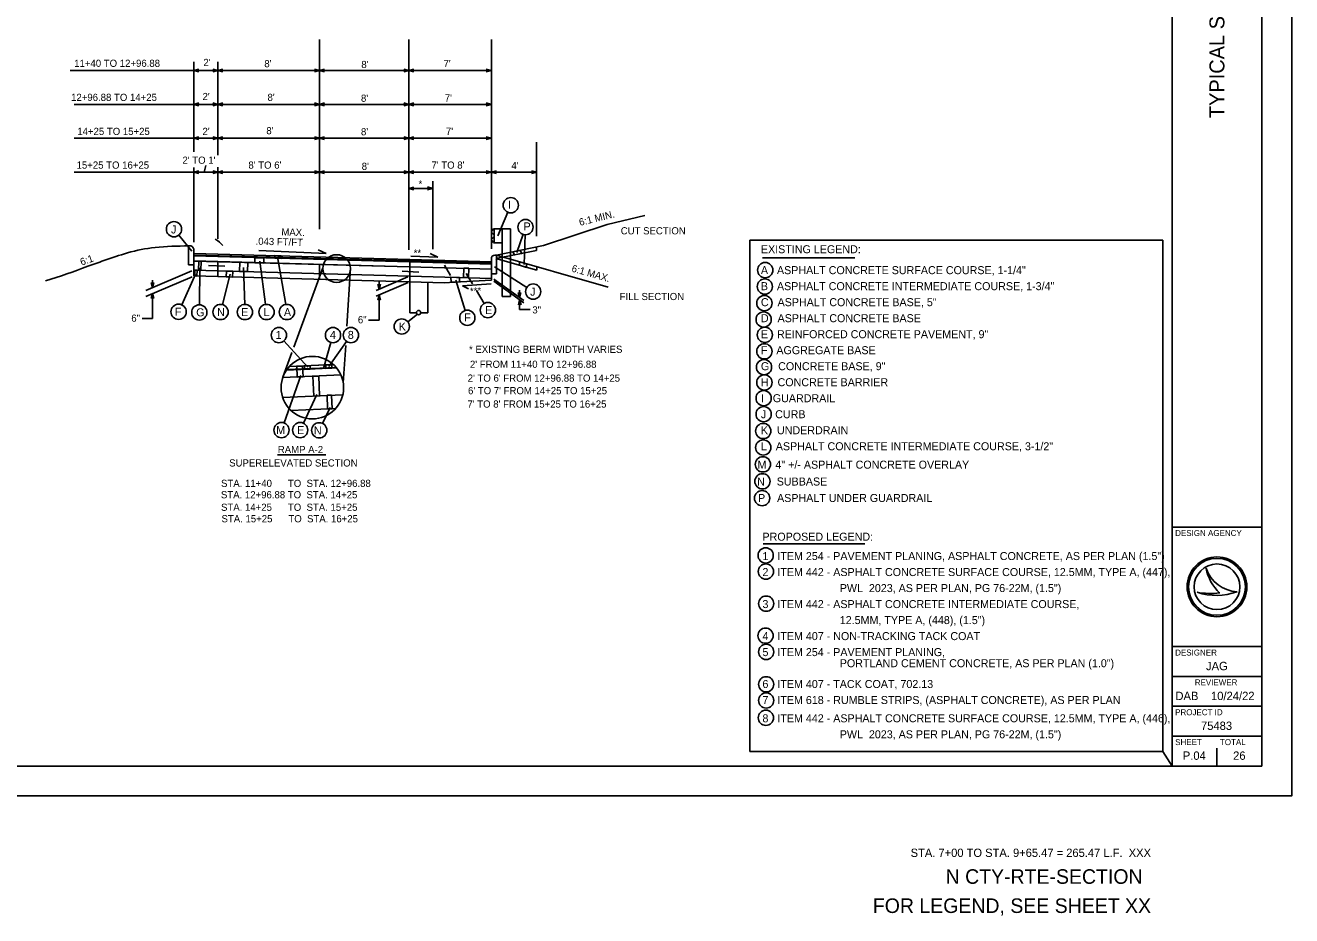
# Model space of a CAD drawing. Extents: x -196 to 300, y -73 to 205.
# Drawn here: x 64 to 170, y -10 to 64.5 of the extents above; entities that cross this region are included whole.
import ezdxf

# ---------------------------------------------------------------- set-up
doc = ezdxf.new("R2010")
doc.units = 0
for name, color, linetype in [('Level 4', 7, 'Continuous'), ('Level 59', 7, 'Continuous'), ('Level 6', 7, 'Continuous'), ('Level 60', 7, 'Continuous'), ('Level 7', 7, 'Continuous'), ('SH_Border', 7, 'Continuous'), ('SH_Cut_Line', 7, 'Continuous'), ('SH_Data', 7, 'Continuous')]:
    doc.layers.add(name, color=color, linetype=linetype)

msp = doc.modelspace()

# ---------------------------------------------------------------- linework, layer by layer
at = {"layer": 'Level 4'}
for p, q in [((88.63, 47.44), (88.63, 63.3)), ((96.11, 45.71), (96.11, 63.3)), ((103.02, 45.78), (103.02, 63.3)), ((67.78, 60.72), (78.13, 60.72)), ((78.13, 53.92), (78.13, 61.44)), ((78.13, 60.72), (80.13, 60.72)), ((80.13, 53.63), (80.13, 61.44)), ((80.13, 60.72), (88.63, 60.72)), ((88.48, 60.74), (88.9, 60.74)), ((88.63, 60.72), (96.11, 60.72)), ((96.11, 60.72), (103.02, 60.72)), ((68.11, 57.88), (78.13, 57.88)), ((78.13, 57.88), (80.13, 57.88)), ((80.13, 57.88), (88.63, 57.88)), ((88.48, 57.9), (88.9, 57.9)), ((88.63, 57.88), (96.11, 57.88)), ((96.11, 57.88), (103.02, 57.88)), ((68.11, 55.04), (78.13, 55.04)), ((78.13, 55.04), (80.13, 55.04)), ((80.13, 55.04), (88.63, 55.04)), ((80.13, 54.28), (80.13, 54.67)), ((88.48, 55.06), (88.9, 55.06)), ((88.63, 55.04), (96.11, 55.04)), ((96.11, 55.04), (103.02, 55.04)), ((106.81, 46.86), (106.81, 54.72)), ((68.11, 52.2), (78.13, 52.2)), ((78.13, 46.34), (78.13, 52.59)), ((78.13, 52.2), (80.13, 52.2)), ((79.12, 52.76), (79, 52.21)), ((80.13, 46.63), (80.13, 52.62)), ((80.13, 52.2), (88.63, 52.2)), ((88.48, 52.22), (88.9, 52.22)), ((88.63, 52.2), (96.11, 52.2)), ((96.11, 52.2), (106.81, 52.2)), ((98.11, 45.75), (98.11, 51.45)), ((96.11, 50.85), (98.11, 50.85)), ((83.56, 45.65), (89.19, 45.4)), ((89.19, 45.4), (88.52, 45.72)), ((96.29, 45.17), (98.55, 45.09)), ((98.55, 45.09), (97.89, 45.41)), ((77.95, 43.94), (74.11, 42.31)), ((77.98, 43.46), (74.11, 41.81)), ((74.67, 42.54), (74.67, 43.17)), ((96.03, 43.44), (93.37, 42.31)), ((96.06, 42.96), (93.39, 41.82)), ((93.63, 42.42), (93.63, 43.05)), ((100.6, 42.69), (103, 42.86)), ((100.6, 42.69), (101.12, 42.43)), ((103.22, 43.25), (105.74, 41.46)), ((103.22, 43.07), (105.75, 41.28)), ((74.67, 39.95), (74.67, 42.05)), ((93.63, 39.82), (93.63, 41.92)), ((105.38, 41.71), (105.38, 42.34)), ((105.39, 40.71), (105.39, 41.53)), ((106.27, 40.71), (105.39, 40.71)), ((73.79, 39.95), (74.67, 39.95)), ((92.75, 39.82), (93.63, 39.82)), ((85.12, 28.55), (89.18, 28.55))]:
    msp.add_line(p, q, dxfattribs=at)
for points in [[(78.55, 60.61), (78.13, 60.72), (78.55, 60.83)], [(79.71, 60.84), (80.13, 60.72), (79.71, 60.61)], [(80.55, 60.61), (80.13, 60.72), (80.55, 60.83)], [(88.21, 60.84), (88.63, 60.72), (88.21, 60.61)], [(89.05, 60.61), (88.63, 60.72), (89.05, 60.83)], [(95.69, 60.84), (96.11, 60.72), (95.69, 60.61)], [(96.53, 60.61), (96.11, 60.72), (96.53, 60.83)], [(102.6, 60.84), (103.02, 60.72), (102.6, 60.61)], [(78.55, 57.77), (78.13, 57.88), (78.55, 58)], [(79.71, 58), (80.13, 57.88), (79.71, 57.77)], [(80.55, 57.77), (80.13, 57.88), (80.55, 58)], [(88.21, 58), (88.63, 57.88), (88.21, 57.77)], [(89.05, 57.77), (88.63, 57.88), (89.05, 58)], [(95.69, 58), (96.11, 57.88), (95.69, 57.77)], [(96.53, 57.77), (96.11, 57.88), (96.53, 58)], [(102.6, 58), (103.02, 57.88), (102.6, 57.77)], [(78.55, 54.93), (78.13, 55.04), (78.55, 55.16)], [(79.71, 55.16), (80.13, 55.04), (79.71, 54.93)], [(80.55, 54.93), (80.13, 55.04), (80.55, 55.16)], [(88.21, 55.16), (88.63, 55.04), (88.21, 54.93)], [(89.05, 54.93), (88.63, 55.04), (89.05, 55.16)], [(95.69, 55.16), (96.11, 55.04), (95.69, 54.93)], [(96.53, 54.93), (96.11, 55.04), (96.53, 55.16)], [(102.6, 55.16), (103.02, 55.04), (102.6, 54.93)], [(78.55, 52.09), (78.13, 52.2), (78.55, 52.32)], [(79.71, 52.32), (80.13, 52.2), (79.71, 52.09)], [(80.55, 52.09), (80.13, 52.2), (80.55, 52.32)], [(88.21, 52.32), (88.63, 52.2), (88.21, 52.09)], [(89.05, 52.09), (88.63, 52.2), (89.05, 52.32)], [(95.69, 52.32), (96.11, 52.2), (95.69, 52.09)], [(96.53, 52.09), (96.11, 52.2), (96.53, 52.32)], [(102.6, 52.32), (103.02, 52.2), (102.6, 52.09)], [(103.44, 52.09), (103.02, 52.2), (103.44, 52.32)], [(106.39, 52.32), (106.81, 52.2), (106.39, 52.09)], [(96.53, 50.73), (96.11, 50.85), (96.53, 50.96)], [(97.69, 50.97), (98.11, 50.85), (97.69, 50.74)], [(74.78, 42.96), (74.67, 42.54), (74.56, 42.96)], [(93.74, 42.84), (93.63, 42.42), (93.51, 42.84)], [(74.55, 41.63), (74.67, 42.05), (74.78, 41.63)], [(93.51, 41.5), (93.63, 41.92), (93.74, 41.5)], [(105.27, 42.13), (105.38, 41.71), (105.49, 42.13)], [(105.51, 41.11), (105.39, 41.53), (105.28, 41.11)]]:
    msp.add_lwpolyline(points, dxfattribs=at)
for points in [[(104.83, 45.54), (105.44, 45.66), (105.57, 45.4), (104.96, 45.28)], [(105.37, 44.7), (105.97, 44.53), (105.97, 44.24), (105.37, 44.41)]]:
    msp.add_lwpolyline(points, close=True, dxfattribs=at)
at = {"layer": 'Level 59'}
for p, q in [((103.57, 46.87), (104.4, 48.85)), ((77.95, 45.6), (76.86, 46.93)), ((105.16, 45.48), (105.68, 47.01)), ((105.77, 44.48), (105.86, 46.98)), ((84.12, 41.14), (83.65, 44.77)), ((85.81, 41.13), (85.13, 45.11)), ((125.72, 45.04), (133.45, 45.04)), ((77.11, 41.1), (78.27, 43.66)), ((78.59, 41.11), (78.63, 44.2)), ((80.52, 41.12), (81.15, 43.66)), ((82.38, 41.14), (82.29, 44.23)), ((100.92, 43.73), (101.44, 42.86)), ((103.28, 44.28), (105.98, 42.55)), ((100.04, 43.17), (100.83, 40.63)), ((101.77, 42.29), (102.41, 41.21)), ((96.83, 40.31), (96.02, 39.68)), ((85.66, 38.08), (87.66, 35.89)), ((89.59, 37.95), (88.98, 35.77)), ((90.91, 38.04), (89.43, 35.93)), ((85.67, 31.22), (87.07, 35.18)), ((87.29, 31.2), (88.42, 33.6)), ((88.9, 31.18), (89.53, 32.5)), ((125.78, 21.1), (134.29, 21.1)), ((159.22, 3.72), (160, 2.5))]:
    msp.add_line(p, q, dxfattribs=at)
for points in [[(78.5, 44), (78.53, 44.76), (78.74, 44.75), (78.72, 43.99)], [(78.2, 43.52), (78.21, 44.01), (78.39, 44), (78.38, 43.51)], [(89.18, 35.78), (89.67, 35.81), (89.66, 36.09), (89.17, 36.07)], [(86.78, 35.06), (87.27, 35.08), (87.22, 35.98), (86.73, 35.96)], [(87.38, 35.7), (87.86, 35.72), (87.86, 36.01), (87.37, 35.99)], [(88.16, 33.47), (88.65, 33.49), (88.57, 35.14), (88.09, 35.12)], [(89.32, 32.4), (89.7, 32.41), (89.65, 33.54), (89.27, 33.53)]]:
    msp.add_lwpolyline(points, close=True, dxfattribs=at)
for centre in [(104.65, 49.44), (76.46, 47.43), (105.88, 47.61), (125.94, 44.01), (106.52, 42.21), (125.91, 42.63), (125.87, 41.25), (76.85, 40.52), (78.58, 40.47), (80.36, 40.5), (82.4, 40.5), (84.21, 40.5), (85.91, 40.5), (101.01, 40.02), (102.73, 40.66), (125.81, 39.87), (95.52, 39.29), (125.91, 38.59), (85.24, 38.57), (89.77, 38.57), (91.27, 38.57), (125.87, 37.21), (125.84, 35.89), (125.87, 34.61), (125.81, 33.29), (125.81, 31.95), (85.46, 30.62), (87.02, 30.62), (88.62, 30.6), (125.78, 30.54), (125.78, 29.16), (125.75, 27.75), (125.71, 26.33), (125.68, 24.92), (125.98, 20.13), (126, 18.78), (126.02, 16.09), (125.97, 13.41), (126.02, 12.05), (126.02, 9.34), (126.02, 7.99), (126, 6.54)]:
    msp.add_circle(centre, 0.639, dxfattribs=at)
at = {"layer": 'Level 6'}
for p, q in [((107.38, 46.06), (112.7, 47.82)), ((112.7, 47.82), (115.87, 48.59)), ((103.04, 47.24), (103.19, 47.45)), ((103.24, 46.99), (103.05, 47.13)), ((103.05, 46.62), (103.24, 46.77)), ((103.19, 47.45), (103.27, 47.46)), ((103.94, 47.46), (103.27, 47.46)), ((103.27, 46.29), (103.27, 47.46)), ((103.94, 47.46), (103.94, 45.21)), ((103.94, 47.46), (104.61, 47.46)), ((104.61, 44.96), (104.61, 47.46)), ((77.68, 44.46), (77.68, 46.03)), ((77.68, 46.03), (77.86, 46.03)), ((78.13, 43.52), (78.13, 45.63)), ((103.19, 46.31), (103.04, 46.51)), ((103.19, 46.31), (103.27, 46.29)), ((103.94, 46.29), (103.27, 46.29)), ((103.41, 44.97), (106.81, 45.66)), ((103.44, 45.26), (107.38, 46.06)), ((106.81, 45.94), (106.81, 45.66)), ((78.13, 45.19), (96.19, 44.7)), ((78.13, 44.79), (96.15, 44.29)), ((78.13, 44.77), (96.19, 44.27)), ((80.13, 44.73), (80.13, 43.47)), ((96.19, 44.7), (103.03, 44.51)), ((96.19, 43.03), (96.19, 44.69)), ((103.03, 43.18), (103.03, 44.97)), ((103.31, 45.26), (103.44, 45.26)), ((103.41, 44.97), (106.82, 44.01)), ((103.44, 43.7), (103.44, 45.26)), ((103.44, 45.26), (112.8, 42.58)), ((103.94, 41.79), (103.94, 45.21)), ((104.61, 44.96), (104.61, 41.79)), ((77.68, 44.46), (78.13, 44.46)), ((78.13, 44.01), (80.13, 43.95)), ((80.13, 43.47), (78.13, 43.52)), ((79.35, 44.4), (80.72, 44.34)), ((80.13, 43.95), (96.19, 43.51)), ((80.13, 43.47), (96.19, 43.03)), ((88.63, 43.23), (88.63, 44.48)), ((95.57, 43.92), (96.95, 43.85)), ((96.15, 44.29), (103.03, 44.1)), ((96.19, 43.51), (103.03, 43.32)), ((103.03, 43.7), (103.44, 43.7)), ((106.82, 44.3), (106.82, 44.01)), ((96.19, 43.03), (99.08, 42.95)), ((96.19, 40.42), (96.19, 43.03)), ((97.7, 40.42), (97.7, 42.98)), ((99.08, 42.95), (100.43, 43.04)), ((100.43, 43.04), (103.03, 43.18)), ((104.61, 41.79), (103.94, 41.79)), ((96.19, 40.42), (96.75, 40.42)), ((97.11, 40.42), (97.7, 40.42)), ((86.1, 35.93), (88.56, 36.04)), ((85.56, 35.01), (90.44, 35.23)), ((85.9, 35.68), (90.03, 35.87)), ((85.55, 33.35), (90.6, 33.58)), ((86.24, 32.26), (90, 32.43))]:
    msp.add_line(p, q, dxfattribs=at)
msp.add_circle((96.93, 40.45), 0.18, dxfattribs=at)
for centre, radius, start, end in [((103.1, 47.2), 0.0781, 144.0839, 232.1285), ((103.19, 46.83), 0.0781, 307.8715, 360), ((77.05, 28.72), 17.33, 97.2009, 104.9698), ((77.41, 19.98), 26.05, 89.4083, 95.577), ((77.77, 45.68), 0.361, 351.8333, 75.1388), ((103.1, 46.56), 0.0781, 127.8715, 215.9161), ((60.39, 70.45), 27.59, 288.763, 291.6971), ((89.64, -11.32), 59.28, 106.7267, 108.7442), ((103.31, 44.97), 0.287, 91.0789, 181.0478), ((52.57, 87.51), 46.29, 286.4816, 291.1285)]:
    msp.add_arc(centre, radius, start, end, dxfattribs=at)
at = {"layer": 'Level 60'}
for points in [[(81.95, 43.89), (81.97, 44.66), (82.63, 44.64), (82.61, 43.88)], [(83.22, 44.62), (83.24, 45.05), (83.98, 45.03), (83.97, 44.6)], [(84.89, 45.01), (84.89, 45.22), (85.43, 45.19), (85.42, 44.98)], [(80.84, 43.44), (80.85, 43.92), (81.38, 43.91), (81.37, 43.42)], [(100.7, 43.39), (100.72, 44.17), (101.13, 44.16), (101.11, 43.38)], [(99.65, 42.99), (100.35, 43.04), (100.35, 43.4), (99.62, 43.42)]]:
    msp.add_lwpolyline(points, close=True, dxfattribs=at)
at = {"layer": 'Level 7'}
for p, q in [((78.12, 45.27), (96.19, 44.78)), ((78.12, 45.19), (96.18, 44.69)), ((78.13, 45.4), (96.19, 44.9)), ((96.18, 44.69), (103.02, 44.5)), ((96.19, 44.9), (103.03, 44.71)), ((96.19, 44.78), (103.03, 44.59)), ((86.49, 37.56), (88.91, 44.21)), ((90.93, 39.33), (91.23, 44.16)), ((99.11, 44.43), (99.61, 43.57)), ((85.57, 35.05), (86.32, 37.12)), ((90.63, 34.56), (90.83, 37.7)), ((86.1, 35.93), (89.82, 36.1)), ((85.87, 35.64), (90.07, 35.82))]:
    msp.add_line(p, q, dxfattribs=at)
for centre, radius in [((90.07, 44.14), 1.16), ((88.04, 34.17), 2.62)]:
    msp.add_circle(centre, radius, dxfattribs=at)
msp.add_arc((78.98, 44.89), 1.95, 36.8194, 61.1597, dxfattribs=at)
at = {"layer": 'SH_Border'}
for p, q in [((160, 2.5), (160, 107.5)), ((160, 22.5), (167.5, 22.5)), ((160, 12.5), (167.5, 12.5)), ((160, 10), (167.5, 10)), ((160, 7.5), (167.5, 7.5)), ((160, 5), (167.5, 5))]:
    msp.add_line(p, q, dxfattribs=at)
msp.add_lwpolyline([(7.5, 107.5), (167.5, 107.5), (167.5, 2.5), (7.5, 2.5)], close=True, dxfattribs=at)
at = {"layer": 'SH_Cut_Line'}
msp.add_lwpolyline([(0, 0), (170, 0), (170, 110), (0, 110)], close=True, dxfattribs=at)
at = {"layer": 'SH_Data'}
for p, q in [((159.22, 46.51), (124.66, 46.51)), ((124.66, 46.51), (124.66, 3.72)), ((159.22, 46.51), (159.22, 3.72)), ((162.84, 19.05), (162.84, 19.05)), ((162.09, 17.05), (162.09, 17.05)), ((163.75, 17.5), (163.75, 17.5)), ((165.44, 17.09), (165.44, 17.09)), ((159.22, 3.72), (124.66, 3.72)), ((161.88, 3.37), (161.88, 3.37)), ((163.75, 2.5), (163.75, 4))]:
    msp.add_line(p, q, dxfattribs=at)
for radius in [2.5, 2.38, 2.38, 1.91]:
    msp.add_circle((163.75, 17.5), radius, dxfattribs=at)
for centre, radius, start, end in [((165.58, 19.99), 2.9, 198.9257, 198.9319), ((166.73, 19.85), 3.98, 191.6379, 191.6421), ((165.58, 19.99), 2.9, 198.9319, 267.1657), ((166.73, 19.85), 3.98, 191.6421, 226.0947), ((163.7, 21.85), 5.07, 251.4576, 290.0832), ((163.24, 23.27), 6.33, 259.4964, 259.4995), ((163.7, 21.85), 5.07, 251.4527, 251.4576), ((163.24, 23.27), 6.33, 259.4995, 276.6672)]:
    msp.add_arc(centre, radius, start, end, dxfattribs=at)

# ---------------------------------------------------------------- texts
at = {"layer": 'Level 4'}
for s, height, p in [('11+40 TO 12+96.88', 0.6, (68.11, 61.02)), ("2'", 0.6, (78.92, 61.09)), ("8'", 0.6, (84.02, 60.99)), ("8'", 0.6, (92.14, 60.92)), ("7'", 0.6, (99.02, 61)), ('12+96.88 TO 14+25', 0.6, (67.85, 58.17)), ("2'", 0.6, (78.85, 58.24)), ("8'", 0.6, (84.29, 58.17)), ("8'", 0.6, (92.11, 58.1)), ("7'", 0.6, (99.12, 58.12)), ('14+25 TO 15+25', 0.6, (68.37, 55.32)), ("2'", 0.6, (78.85, 55.32)), ("8'", 0.6, (84.19, 55.38)), ("8'", 0.6, (92.11, 55.29)), ("7'", 0.6, (99.22, 55.33)), ('15+25 TO 16+25', 0.6, (68.31, 52.5)), ("2' TO 1'", 0.6, (77.17, 52.91)), ("8' TO 6'", 0.6, (82.69, 52.5)), ("8'", 0.6, (92.17, 52.4)), ("7' TO 8'", 0.6, (98.01, 52.5)), ("4'", 0.6, (104.7, 52.46)), ('*', 0.6, (96.93, 50.92)), ('CUT SECTION', 0.6, (113.85, 47)), ('**', 0.6, (96.52, 45.14)), ('FILL SECTION', 0.6, (113.76, 41.5)), ('6"', 0.6, (72.89, 39.69)), ('3"', 0.6, (106.45, 40.38)), ('6"', 0.6, (91.85, 39.56)), ('* EXISTING BERM WIDTH VARIES', 0.6, (101.15, 37.08)), ("2' FROM 11+40 TO 12+96.88", 0.6, (101.23, 35.83)), ("2' TO 6' FROM 12+96.88 TO 14+25", 0.6, (101.04, 34.67)), ("6' TO 7' FROM 14+25 TO 15+25", 0.6, (101.07, 33.62)), ("7' TO 8' FROM 15+25 TO 16+25", 0.6, (101.02, 32.5)), ('RAMP A-2', 0.6, (85.15, 28.69)), ('SUPERELEVATED SECTION', 0.6, (81.08, 27.57)), ('STA. 11+40      TO  STA. 12+96.88', 0.6, (80.4, 25.86)), ('STA. 12+96.88 TO  STA. 14+25', 0.6, (80.39, 24.91)), ('STA. 14+25      TO  STA. 15+25', 0.6, (80.4, 23.86)), ('STA. 15+25      TO  STA. 16+25', 0.6, (80.44, 22.9)), ('STA. 7+00 TO STA. 9+65.47 = 265.47 L.F.  XXX', 0.6966, (138.11, -5.11)), ('N CTY-RTE-SECTION', 1.219, (141.04, -7.36)), ('FOR LEGEND, SEE SHEET XX', 1.219, (134.95, -9.8))]:
    msp.add_text(s, height=height, dxfattribs=at).set_placement(p)
for s, rotation, p in [('6:1 MIN.', 13.7951, (110.44, 47.71)), ('.043 FT/FT', 358.4259, (83.28, 46.14)), ('MAX.', 358.4259, (85.44, 46.91)), ('6:1', 19.5301, (68.73, 44.38)), ('6:1 MAX.', 344.048, (109.69, 43.9)), ('***', 4.0774, (101.26, 41.94))]:
    msp.add_text(s, height=0.6, rotation=rotation, dxfattribs=at).set_placement(p)
at = {"layer": 'Level 59'}
for s, height, p in [('I', 0.67, (104.41, 49.15)), ('J', 0.67, (76.21, 47.08)), ('P', 0.67, (105.72, 47.33)), ('EXISTING LEGEND:', 0.6698, (125.58, 45.42)), ('A   ASPHALT CONCRETE SURFACE COURSE, 1-1/4"', 0.6698, (125.58, 43.67)), ('J', 0.67, (106.27, 41.87)), ('B   ASPHALT CONCRETE INTERMEDIATE COURSE, 1-3/4"', 0.6698, (125.58, 42.33)), ('C   ASPHALT CONCRETE BASE, 5"', 0.6698, (125.58, 40.99)), ('F', 0.67, (76.54, 40.19)), ('G', 0.67, (78.32, 40.14)), ('N', 0.67, (80.07, 40.16)), ('E', 0.67, (82.08, 40.16)), ('L', 0.67, (83.96, 40.16)), ('A', 0.67, (85.66, 40.16)), ('F', 0.67, (100.75, 39.71)), ('E', 0.67, (102.5, 40.33)), ('D   ASPHALT CONCRETE BASE', 0.6698, (125.58, 39.65)), ('K', 0.67, (95.27, 38.95)), ('1', 0.67, (84.97, 38.25)), ('4', 0.67, (89.51, 38.25)), ('8', 0.67, (91.01, 38.25)), ('E   REINFORCED CONCRETE PAVEMENT, 9"', 0.6698, (125.58, 38.31)), ('F   AGGREGATE BASE', 0.6698, (125.58, 36.97)), ('G   CONCRETE BASE, 9"', 0.6698, (125.58, 35.63)), ('H   CONCRETE BARRIER', 0.6698, (125.58, 34.29)), ('I   GUARDRAIL ', 0.6698, (125.58, 32.95)), ('J   CURB', 0.67, (125.58, 31.61)), ('M', 0.67, (85.02, 30.28)), ('E', 0.67, (86.76, 30.28)), ('N', 0.67, (88.17, 30.25)), ('K   UNDERDRAIN ', 0.6698, (125.58, 30.27)), ('L   ASPHALT CONCRETE INTERMEDIATE COURSE, 3-1/2"          ', 0.6698, (125.58, 28.93)), ('M   4" +/- ASPHALT CONCRETE OVERLAY   ', 0.6698, (125.3, 27.39)), ('N    SUBBASE', 0.6698, (125.26, 25.98)), ('P    ASPHALT UNDER GUARDRAIL', 0.6698, (125.34, 24.6)), ('PROPOSED LEGEND:', 0.6698, (125.71, 21.36)), ('1   ITEM 254 - PAVEMENT PLANING, ASPHALT CONCRETE, AS PER PLAN (1.5")', 0.6698, (125.71, 19.74)), ('2   ITEM 442 - ASPHALT CONCRETE SURFACE COURSE, 12.5MM, TYPE A, (447),', 0.6698, (125.71, 18.4)), ('                          PWL  2023, AS PER PLAN, PG 76-22M, (1.5")', 0.6698, (125.71, 17.06)), ('3   ITEM 442 - ASPHALT CONCRETE INTERMEDIATE COURSE,', 0.6698, (125.71, 15.72)), ('                          12.5MM, TYPE A, (448), (1.5")', 0.6698, (125.71, 14.38)), ('4   ITEM 407 - NON-TRACKING TACK COAT', 0.6698, (125.71, 13.04)), ('5   ITEM 254 - PAVEMENT PLANING, ', 0.6698, (125.71, 11.7)), ('                          PORTLAND CEMENT CONCRETE, AS PER PLAN (1.0")', 0.6698, (125.71, 10.77)), ('6   ITEM 407 - TACK COAT, 702.13', 0.6698, (125.71, 9.03)), ('7   ITEM 618 - RUMBLE STRIPS, (ASPHALT CONCRETE), AS PER PLAN', 0.6698, (125.71, 7.69)), ('8   ITEM 442 - ASPHALT CONCRETE SURFACE COURSE, 12.5MM, TYPE A, (446),', 0.6698, (125.71, 6.16)), ('                          PWL  2023, AS PER PLAN, PG 76-22M, (1.5")', 0.6698, (125.71, 4.82))]:
    msp.add_text(s, height=height, dxfattribs=at).set_placement(p)
at = {"layer": 'SH_Data'}
msp.add_text('TYPICAL SECTIONS', height=1.25, rotation=90, dxfattribs=at).set_placement((164.37, 56.73))
for s, height, p in [('DESIGN AGENCY', 0.5, (160.25, 21.75)), ('DESIGNER', 0.5, (160.25, 11.75)), ('JAG', 0.7, (162.83, 10.52)), ('REVIEWER', 0.5, (161.89, 9.25)), ('DAB', 0.7, (160.27, 8.02)), ('10/24/22', 0.7, (163.25, 8.02)), ('PROJECT ID', 0.5, (160.25, 6.75)), ('75483', 0.7, (162.41, 5.52)), ('SHEET', 0.5, (160.25, 4.25)), ('TOTAL', 0.5, (164, 4.25)), ('P.04', 0.7, (160.89, 3.02)), ('26', 0.7, (165.1, 3.02))]:
    msp.add_text(s, height=height, dxfattribs=at).set_placement(p)

doc.saveas('drawing.dxf')
